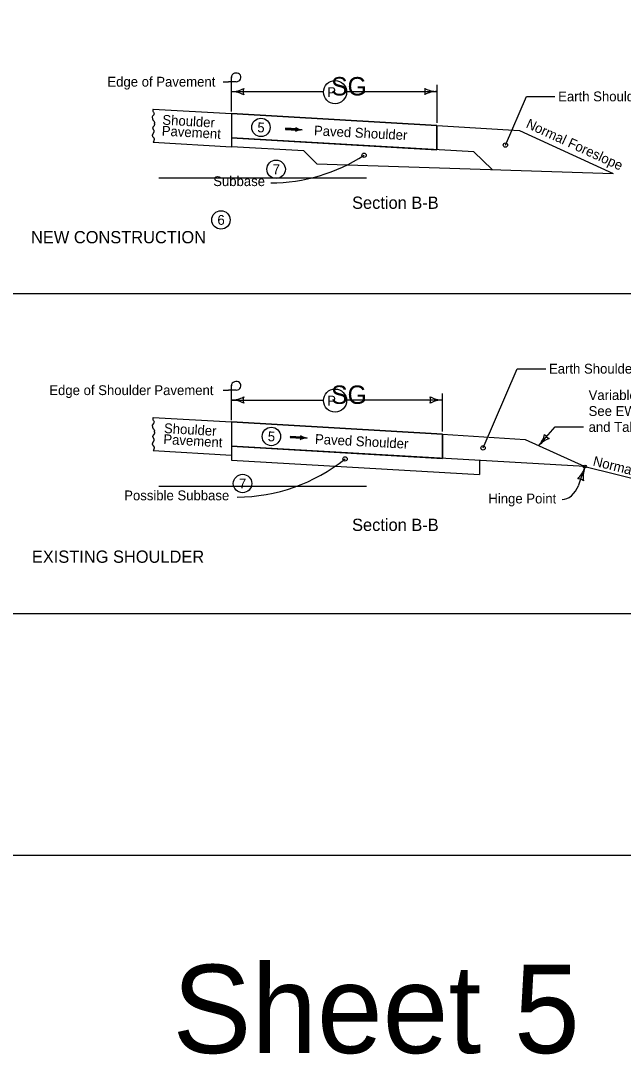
# Model space of a CAD drawing. Extents: x 9538 to 81668, y 7600 to 11751.
# Drawn here: x 25461 to 26443, y 7600 to 9286 of the extents above; entities that cross this region are included whole.
import ezdxf

# ---------------------------------------------------------------- set-up
doc = ezdxf.new("R2010")
doc.units = 0
for name, color, linetype in [('Default', 7, 'Continuous'), ('DsnShtMinorGrid13', 7, 'Continuous'), ('DsnShtMinorGrid14', 7, 'Continuous'), ('dsnStdDimension', 7, 'Continuous'), ('dsnStdNameDate', 7, 'Continuous'), ('dsnStdNote', 7, 'Continuous'), ('dsnStdShading', 7, 'Continuous'), ('dsnStdTable', 7, 'Continuous'), ('Level 13', 7, 'Continuous')]:
    doc.layers.add(name, color=color, linetype=linetype)

msp = doc.modelspace()

# ---------------------------------------------------------------- linework, layer by layer
at = {"layer": 'Default'}
msp.add_lwpolyline([(24532.5, 9944), (27667.6, 9944), (27667.6, 7924), (24532.5, 7924)], close=True, dxfattribs=at)
at = {"layer": 'DsnShtMinorGrid13'}
for centre in [(25852.2, 9111.5), (25877, 9043.2), (25787, 8960.6), (25869.2, 8607.5), (25822.2, 8530.8)]:
    msp.add_circle(centre, 15, dxfattribs=at)
at = {"layer": 'DsnShtMinorGrid14'}
for centre in [(26250.7, 9082.6), (26020.4, 9066.1), (26214.3, 8588.9), (25989.3, 8570.8)]:
    msp.add_circle(centre, 3.54, dxfattribs=at)
at = {"layer": 'dsnStdDimension'}
for p, q in [((25804.1, 9169.8), (25954.1, 9169.8)), ((25991.9, 9170), (26139.3, 9170)), ((26139.3, 9119.1), (26139.3, 9180.8)), ((25804.1, 8666.9), (25954.1, 8666.9)), ((25991.9, 8667), (26148.4, 8667)), ((26148.4, 8615.7), (26148.4, 8677.4))]:
    msp.add_line(p, q, dxfattribs=at)
for centre in [(25973, 9169), (25973, 8666)]:
    msp.add_circle(centre, 18.9, dxfattribs=at)
for centre, radius, start, end in [((25804.1, 9212.3), 42.5, 270, 298.0725), ((25804.1, 9127.3), 42.5, 61.9275, 90), ((25839.7, 9169.8), 16.4, 162.2666, 197.7334), ((26103.6, 9170), 16.4, 342.2666, 17.7333), ((26139.3, 9212.5), 42.5, 241.9275, 270), ((26139.3, 9127.5), 42.5, 90, 118.0725), ((25867.5, 9303), 282, 270.132, 302.8427), ((25804.1, 8709.4), 42.5, 270, 298.0725), ((25804.1, 8624.4), 42.5, 61.9275, 90), ((25839.7, 8666.9), 16.4, 162.2666, 197.7334), ((26112.7, 8667), 16.4, 342.2666, 17.7333), ((26148.4, 8709.5), 42.5, 241.9275, 270), ((26148.4, 8624.5), 42.5, 90, 118.0725), ((25812.6, 8790.7), 282, 270.132, 308.7946)]:
    msp.add_arc(centre, radius, start, end, dxfattribs=at)
at = {"layer": 'dsnStdNameDate'}
msp.add_line((26703.1, 8840), (24547.5, 8840), dxfattribs=at)
at = {"layer": 'dsnStdNote'}
for p, q in [((25804.1, 9173.1), (25804.1, 9194)), ((25790.7, 9186), (25799.4, 9186)), ((25811.9, 9186), (25799.4, 9186)), ((25804.1, 9137.2), (25804.1, 9173.1)), ((26250.7, 9082.6), (26285, 9162)), ((26285, 9162), (26331.4, 9162)), ((25910.4, 9108.1), (25892.2, 9109.1)), ((25910.3, 9107.1), (25910.3, 9107.1)), ((25910.5, 9109.1), (25910.5, 9109.1)), ((26214.3, 8588.9), (26270, 8718)), ((26270, 8718), (26316.4, 8718)), ((25790.7, 8683), (25799.4, 8683)), ((25811.9, 8683), (25799.4, 8683)), ((25804.1, 8670.2), (25804.1, 8691)), ((25804.1, 8634.2), (25804.1, 8670.2)), ((26305.3, 8592.6), (26331.9, 8623)), ((26331.9, 8623), (26378.3, 8623)), ((25918.3, 8605.6), (25900.1, 8606.6)), ((25918.2, 8604.7), (25918.2, 8604.7)), ((25918.3, 8606.6), (25918.3, 8606.6)), ((26370.4, 8528.4), (26379.9, 8555.9))]:
    msp.add_line(p, q, dxfattribs=at)
for points in [[(25910.5, 9109), (25892.3, 9110.1), (25892.2, 9108.2), (25910.3, 9107.1), (25910.4, 9108.8), (25892.5, 9109.9), (25892.5, 9108.4), (25910, 9107.4), (25910.1, 9108.5), (25892.8, 9109.6), (25892.7, 9108.6), (25909.7, 9107.6), (25909.8, 9108.3), (25892.9, 9109.4), (25892.9, 9108.8), (25909.5, 9107.9)], [(25910.1, 9110.3), (25910.8, 9109.1), (25910.7, 9107.5), (25910, 9106.1), (25912.7, 9106.9), (25915.9, 9107.6), (25916.8, 9107.7), (25914.6, 9108.3), (25911.4, 9109.5), (25910.4, 9110), (25910.5, 9106.5), (25915.5, 9107.7), (25910.8, 9109.3), (25910.9, 9106.9), (25914.3, 9107.8), (25911.3, 9108.7), (25911, 9107.3), (25913.2, 9107.8), (25911.6, 9108.3), (25911.5, 9107.7), (25912.2, 9107.8)], [(25918.4, 8606.5), (25900.2, 8607.6), (25900.1, 8605.7), (25918.2, 8604.7), (25918.3, 8606.3), (25900.4, 8607.4), (25900.4, 8605.9), (25917.8, 8604.9), (25918, 8606), (25900.6, 8607.1), (25900.6, 8606.1), (25917.6, 8605.1), (25917.7, 8605.8), (25900.8, 8606.9), (25900.8, 8606.3), (25917.4, 8605.4)], [(25918, 8607.8), (25918.6, 8606.6), (25918.6, 8605), (25917.9, 8603.6), (25920.6, 8604.4), (25923.8, 8605.1), (25924.7, 8605.2), (25922.5, 8605.8), (25919.2, 8607), (25918.3, 8607.5), (25918.4, 8604), (25923.4, 8605.2), (25918.7, 8606.8), (25918.7, 8604.4), (25922.1, 8605.3), (25919.1, 8606.2), (25918.9, 8604.8), (25921.1, 8605.3), (25919.5, 8605.8), (25919.3, 8605.2), (25920.1, 8605.3)]]:
    msp.add_lwpolyline(points, dxfattribs=at)
for centre, radius, start, end in [((26273.3, 8620.6), 42.5, 318.8454, 346.9178), ((26337.3, 8564.6), 42.5, 110.7729, 138.8454), ((26328.7, 8619.4), 16.4, 211.112, 246.5787), ((26339.7, 8569.7), 42.5, 312.9788, 341.0513), ((26420.1, 8542.1), 42.5, 161.0513, 189.1238), ((26368.3, 8522.2), 16.4, 53.3179, 88.7846)]:
    msp.add_arc(centre, radius, start, end, dxfattribs=at)
for centre, major_axis, ratio, start_param, end_param in [((25811.9, 9193.1), (-7.81, 0), 0.913811, 1.570796, 6.283185), ((25906.7, 9108.3), (3.88, 0), 0.913811, 5.202895, 7.237436), ((25918.9, 9087.3), (22.2, 0), 0.913811, 1.537172, 2.061295), ((25921.7, 9127.7), (-22.2, 0), 0.913811, 0.954258, 1.478381), ((25811.9, 8690.2), (-7.81, 0), 0.913811, 1.570796, 6.283185), ((25914.6, 8605.8), (3.88, 0), 0.913811, 5.202895, 7.237436), ((25926.8, 8584.8), (22.2, 0), 0.913811, 1.537172, 2.061295), ((25929.6, 8625.2), (-22.2, 0), 0.913811, 0.954258, 1.478381), ((26343.3, 8566.2), (0, 61.5), 0.559383, 3.141593, 4.048985)]:
    msp.add_ellipse(centre, major_axis=major_axis, ratio=ratio, start_param=start_param, end_param=end_param, dxfattribs=at)
at = {"layer": 'dsnStdShading'}
msp.add_line((24547.5, 8319), (27643.2, 8319), dxfattribs=at)
at = {"layer": 'dsnStdTable'}
for p, q in [((25676.6, 9141.5), (25804.1, 9134.1)), ((25804.1, 9134.1), (25804.1, 9080)), ((25804.1, 9134.1), (26139.2, 9114.6)), ((26139.2, 9114.6), (25804.1, 9134.1)), ((25804.1, 9134.1), (25804.1, 9094.5)), ((26139.2, 9114.6), (26139.2, 9075.1)), ((26139.2, 9114.6), (26274, 9106.2)), ((26139.2, 9075.1), (26139.2, 9114.6)), ((26274, 9106.2), (26426.6, 9036.2)), ((25676.6, 9087.4), (25804.1, 9080)), ((26199.2, 9071.7), (25804.1, 9094.5)), ((25804.1, 9094.5), (26139.2, 9075.1)), ((25921.9, 9073.2), (25804.1, 9080)), ((25921.9, 9073.2), (25943.2, 9052)), ((26199.2, 9071.7), (26229.1, 9042.7)), ((25943.2, 9052), (26426.6, 9036.2)), ((25686, 9029.1), (26024.5, 9029.1)), ((25676.6, 8638.5), (25804.1, 8631.1)), ((25804.1, 8631.1), (25804.1, 8577.1)), ((25804.1, 8631.1), (26148.3, 8611.1)), ((26148.3, 8611.1), (25804.1, 8631.1)), ((25804.1, 8631.1), (25804.1, 8591.5)), ((26147.9, 8611.3), (26147.9, 8611.3)), ((26148.3, 8611.1), (26148.3, 8571.7)), ((26148.3, 8571.7), (26148.3, 8611.1)), ((26148.4, 8611.2), (26283.1, 8602.8)), ((26283.1, 8602.8), (26380.2, 8558.3)), ((25676.6, 8584.5), (25804.1, 8577.1)), ((26380.2, 8558.3), (25804.1, 8591.5)), ((25804.1, 8591.5), (26148.3, 8571.7)), ((25804.1, 8577.1), (25804.1, 8568.7)), ((25804.1, 8568.7), (26208.3, 8545.4)), ((26208.3, 8568.2), (26208.3, 8545.4)), ((26380.2, 8558.3), (26555.1, 8515)), ((25686, 8526.2), (26024.5, 8526.2))]:
    msp.add_line(p, q, dxfattribs=at)
for centre in [(25852.2, 9111.5), (25869.2, 8607.5)]:
    msp.add_circle(centre, 15, dxfattribs=at)
msp.add_ellipse((26380.2, 8558.3), major_axis=(2.58, 0), ratio=0.913811, dxfattribs=at)
for points in [[(25676.6, 9141.5), (25676.1, 9137.9), (25677.1, 9136.4), (25678, 9134.1), (25677.4, 9132), (25675.5, 9129.6), (25675, 9127.7), (25675.5, 9125.4), (25676.3, 9123), (25677.4, 9122.3), (25678.8, 9119.8), (25678.8, 9119)], [(25676.8, 9101.9), (25677, 9102.1), (25677.2, 9102.4), (25677.6, 9102.9), (25677.8, 9103.5), (25678, 9103.8), (25678.1, 9104.1), (25678.2, 9104.8), (25678.2, 9105.4), (25678.2, 9106), (25678.1, 9106.2), (25678.1, 9106.4), (25678.1, 9106.5), (25677.8, 9106.9), (25677.6, 9107.2), (25677.3, 9107.6), (25677, 9108), (25676.9, 9108.3), (25676.7, 9108.6), (25676.5, 9109.1), (25676.3, 9109.7), (25676.2, 9110), (25676.1, 9110.3), (25676.1, 9110.4), (25676.1, 9110.6), (25676.3, 9111.3), (25676.5, 9111.9), (25676.8, 9112.4), (25677.2, 9113), (25677.7, 9113.5), (25678.2, 9114.1), (25678.5, 9114.4), (25678.7, 9114.7), (25678.9, 9115.2), (25679, 9115.7), (25679.1, 9116.2), (25679.2, 9116.4), (25679.2, 9116.5), (25679.2, 9116.6), (25679.1, 9117.1), (25679, 9117.7), (25678.9, 9117.8), (25678.9, 9117.9), (25678.8, 9118), (25678.8, 9118.2), (25678.8, 9119)], [(25676.8, 9101.9), (25676.6, 9101.6), (25676.3, 9101.4), (25676.1, 9101.1), (25675.9, 9100.9), (25675.8, 9100.6), (25675.6, 9100.3), (25675.4, 9099.7), (25675.3, 9099.4), (25675.2, 9099.2), (25675.1, 9098.9), (25675.1, 9098.7), (25675.1, 9098.6), (25675.1, 9098.1), (25675.2, 9097.5), (25675.4, 9097), (25675.7, 9096.5), (25676.1, 9095.9), (25676.6, 9095.3), (25677.1, 9094.8), (25677.4, 9094.5), (25677.6, 9094.1), (25678, 9093.2), (25678.1, 9092.7), (25678.1, 9092.2), (25678.1, 9091.9), (25678, 9091.7), (25677.9, 9091.4), (25677.9, 9091.1), (25677.6, 9089.9), (25677.4, 9089.3), (25677.2, 9088.7), (25677, 9088.1), (25676.8, 9087.9), (25676.7, 9087.6), (25676.6, 9087.4)], [(25676.6, 8638.5), (25676.1, 8634.9), (25677.1, 8633.4), (25678, 8631.1), (25677.4, 8629.1), (25675.5, 8626.7), (25675, 8624.8), (25675.5, 8622.5), (25676.3, 8620.1), (25677.4, 8619.4), (25678.8, 8616.9), (25678.8, 8616)], [(25676.8, 8598.9), (25677, 8599.2), (25677.2, 8599.4), (25677.6, 8600), (25677.8, 8600.6), (25678, 8600.9), (25678.1, 8601.2), (25678.2, 8601.8), (25678.2, 8602.4), (25678.2, 8603), (25678.1, 8603.3), (25678.1, 8603.4), (25678.1, 8603.6), (25677.8, 8603.9), (25677.6, 8604.3), (25677.3, 8604.7), (25677, 8605.1), (25676.9, 8605.3), (25676.7, 8605.6), (25676.5, 8606.2), (25676.3, 8606.8), (25676.2, 8607.1), (25676.1, 8607.4), (25676.1, 8607.5), (25676.1, 8607.6), (25676.3, 8608.4), (25676.5, 8608.9), (25676.8, 8609.4), (25677.2, 8610.1), (25677.7, 8610.6), (25678.2, 8611.1), (25678.5, 8611.4), (25678.7, 8611.8), (25678.9, 8612.3), (25679, 8612.7), (25679.1, 8613.2), (25679.2, 8613.5), (25679.2, 8613.6), (25679.2, 8613.7), (25679.1, 8614.2), (25679, 8614.7), (25678.9, 8614.8), (25678.9, 8615), (25678.8, 8615.1), (25678.8, 8615.2), (25678.8, 8616)], [(25676.8, 8598.9), (25676.6, 8598.7), (25676.3, 8598.4), (25676.1, 8598.2), (25675.9, 8597.9), (25675.8, 8597.6), (25675.6, 8597.4), (25675.4, 8596.8), (25675.3, 8596.5), (25675.2, 8596.2), (25675.1, 8595.9), (25675.1, 8595.8), (25675.1, 8595.6), (25675.1, 8595.1), (25675.2, 8594.6), (25675.4, 8594.1), (25675.7, 8593.6), (25676.1, 8592.9), (25676.6, 8592.4), (25677.1, 8591.8), (25677.4, 8591.5), (25677.6, 8591.2), (25678, 8590.2), (25678.1, 8589.8), (25678.1, 8589.3), (25678.1, 8589), (25678, 8588.7), (25677.9, 8588.4), (25677.9, 8588.1), (25677.6, 8587), (25677.4, 8586.4), (25677.2, 8585.8), (25677, 8585.2), (25676.8, 8584.9), (25676.7, 8584.6), (25676.6, 8584.5)]]:
    msp.add_spline(points, degree=3, dxfattribs=at)

# ---------------------------------------------------------------- texts
at = {"layer": 'DsnShtMinorGrid13'}
for p in [(25846, 9103.8), (25863, 8599.9)]:
    msp.add_text('5', height=16, rotation=356.6997, dxfattribs=at).set_placement(p)
for s, p in [('7', (25871.3, 9035.2)), ('6', (25781.3, 8952.6)), ('7', (25816.4, 8522.8))]:
    msp.add_text(s, height=16, dxfattribs=at).set_placement(p)
at = {"layer": 'dsnStdDimension'}
for s, height, p in [('SG', 30, (25966.7, 9163.6)), ('P', 16, (25960.3, 9161)), ('SG', 30, (25966.7, 8660.6)), ('P', 16, (25960.3, 8658))]:
    msp.add_text(s, height=height, dxfattribs=at).set_placement(p)
at = {"layer": 'dsnStdNote'}
for s, height, p in [('Edge of Pavement', 16, (25601.9, 9178)), ('Earth Shoulder Construction', 16, (26336.8, 9154)), ('Subbase', 16, (25774.4, 9015.8)), ('Section B-B', 20, (26000.8, 8978.7)), ('NEW CONSTRUCTION', 20, (25477.4, 8922.5)), ('Earth Shoulder Construction', 16, (26321.8, 8710)), ('Edge of Shoulder Pavement', 16, (25507.2, 8675)), ('Variable Slope', 16, (26386.4, 8667)), ('See EW-301', 16, (26386.4, 8641)), ('and Tabulation 107-23', 16, (26386.4, 8615)), ('Possible Subbase', 16, (25629.3, 8503.4)), ('Hinge Point', 16, (26223, 8498.3)), ('Section B-B', 20, (26000.8, 8453.4)), ('EXISTING SHOULDER', 20, (25478.8, 8401.5))]:
    msp.add_text(s, height=height, dxfattribs=at).set_placement(p)
for s, rotation, p in [('Shoulder', 356.7346, (25691.2, 9116.1)), ('Normal Foreslope', 335.372, (26283, 9111.8)), ('Pavement', 356.7346, (25690.2, 9098.2)), ('Paved Shoulder ', 357.0678, (25938.4, 9098.5)), ('Shoulder', 356.7346, (25693.8, 8613.2)), ('Pavement', 356.7346, (25692.8, 8595.2)), ('Paved Shoulder ', 356.983, (25940, 8595.5)), ('Normal Foreslope', 346.0988, (26392.4, 8560.3))]:
    msp.add_text(s, height=16, rotation=rotation, dxfattribs=at).set_placement(p)
at = {"layer": 'Level 13'}
msp.add_text('Sheet 5', height=144, dxfattribs=at).set_placement((25708.1, 7602))

doc.saveas('drawing.dxf')
